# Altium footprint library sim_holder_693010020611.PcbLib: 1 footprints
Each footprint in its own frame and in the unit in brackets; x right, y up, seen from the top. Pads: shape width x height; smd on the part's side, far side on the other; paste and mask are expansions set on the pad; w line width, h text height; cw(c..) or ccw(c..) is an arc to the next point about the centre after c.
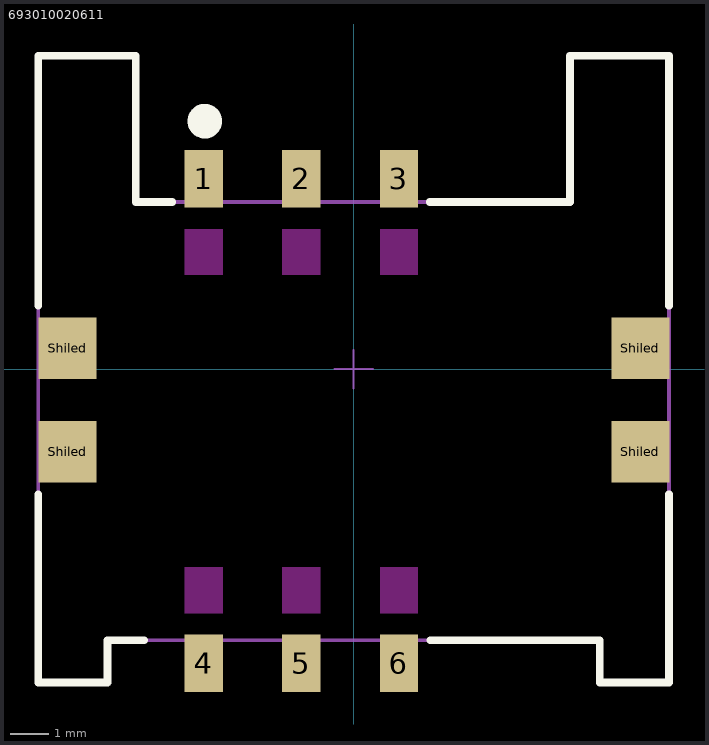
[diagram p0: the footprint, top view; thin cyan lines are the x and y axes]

## 693010020611 [mm] "SIM CARD CONNECTOR HEADER SHIELD ED 6PINS"
height 1.8
pads (10):
  rect 1x1.5 smd: 1(-3.9,4.95) 2(-1.36,4.95) 3(1.18,4.95) 4(-3.9,-7.65) 5(-1.36,-7.65) 6(1.18,-7.65)
  rect 1.5x1.6 smd: Shiled(-7.44,-2.15) Shiled(-7.44,0.55) Shiled(7.46,-2.15) Shiled(7.46,0.55)
Top Layer keep-out:
  region: -3.4,-5.15 -4.4,-5.15 -4.4,-6.35 -3.4,-6.35
  region: -0.86,-5.15 -1.86,-5.15 -1.86,-6.35 -0.86,-6.35
  region: 1.68,-5.15 0.68,-5.15 0.68,-6.35 1.68,-6.35
  rectangle: -4.4,2.45 -3.4,3.65
  rectangle: -1.86,2.45 -0.86,3.65
  rectangle: 0.68,2.45 1.68,3.65
Top Overlay:
  circle w0.5: c-3.87,6.45 r0.2
  lines w0.2: -8.2,-3.25 -8.2,-8.15 -6.4,-8.15 -6.4,-7.05 -5.45,-7.05 ; -8.2,1.65 -8.2,8.15 -5.67,8.15 -5.67,4.35 -4.72,4.35 ; 1.98,4.35 5.63,4.35 5.63,8.15 ; 2,-7.05 6.4,-7.05 6.4,-8.15 8.2,-8.15 8.2,-3.25 ; 8.2,1.65 8.2,8.15 5.63,8.15 ; 5.63,8.15 5.63,8.15
Mechanical 13:
  lines w0.1: 5.63,8.15 8.2,8.15 8.2,-8.15 6.4,-8.15 6.4,-7.05 -6.4,-7.05 -6.4,-8.15 -8.2,-8.15 -8.2,8.15 -5.67,8.15 -5.67,4.35 5.63,4.35 5.63,8.15 ; 5.63,8.15 5.63,8.15
Mechanical 15:
  lines w0.05: -0.5,0 0.5,0 ; 0,-0.5 0,0.5
3D body "693010020611.stp": height 1.82, standoff -0.03, extent -8.2,-8.15 8.2,8.15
